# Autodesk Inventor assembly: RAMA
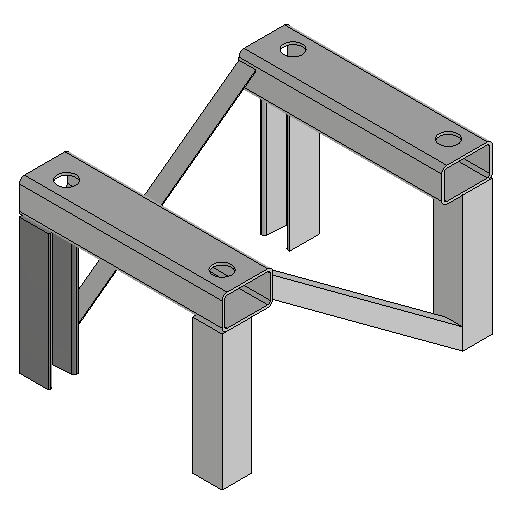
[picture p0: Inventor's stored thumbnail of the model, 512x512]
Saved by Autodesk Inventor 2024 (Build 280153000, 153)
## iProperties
Company: ATC
_FrameDoc: Frame Assembly
_Version: 25.0.0
Created: 2023-03
Part Number: RAMA
Document SubType Name: Assembly
Designer: Andrzej Jaskulski
Checked By: A.J.
Engr Approved By: Andrzej Jaskulski
Mfg Approved By: Andrzej Jaskulski
Authority: A.J.
Author: Andrzej Jaskulski
Title: A.J.: Kurs R2024-MEP
Revision Number: 1/24
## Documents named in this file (10)
- C:\Users\AndJas\Documents\R2024-MEP\Obszar roboczy\SPEC\GOTOWE\SPEC-GOTOWE\Rama\RAMA.iam
- C:\Users\AndJas\Documents\R2024-MEP\Obszar roboczy\SPEC\GOTOWE\SPEC-GOTOWE\Rama\SZKIELET.ipt
- C:\Users\AndJas\Documents\R2024-MEP\Obszar roboczy\SPEC\GOTOWE\SPEC-GOTOWE\Rama\PN C 35x35-01.ipt
- C:\Users\AndJas\Documents\R2024-MEP\Obszar roboczy\SPEC\GOTOWE\SPEC-GOTOWE\Rama\PN C 35x35-02.ipt
- C:\Users\AndJas\Documents\R2024-MEP\Obszar roboczy\SPEC\GOTOWE\SPEC-GOTOWE\Rama\PN C 35x35-03.ipt
- C:\Users\AndJas\Documents\R2024-MEP\Obszar roboczy\SPEC\GOTOWE\SPEC-GOTOWE\Rama\PN C 35x35-04.ipt
- C:\Users\AndJas\Documents\R2024-MEP\Obszar roboczy\SPEC\GOTOWE\SPEC-GOTOWE\Rama\PN 60 x 40 x 3-05.ipt
- C:\Users\AndJas\Documents\R2024-MEP\Obszar roboczy\SPEC\GOTOWE\SPEC-GOTOWE\Rama\PN 60 x 40 x 3-06.ipt
- C:\Users\AndJas\Documents\R2024-MEP\Obszar roboczy\SPEC\GOTOWE\SPEC-GOTOWE\Rama\PN L20x20x3-7.ipt
- C:\Users\AndJas\Documents\R2024-MEP\Obszar roboczy\SPEC\GOTOWE\SPEC-GOTOWE\Rama\PN L20x20x3-8.ipt
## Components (9 placed, 9 different names)
1. SZKIELET:1
2. PN C 35x35-01:1
3. PN C 35x35-02:1
4. PN C 35x35-03:1
5. PN C 35x35-04:1
6. PN 60 x 40 x 3-05:1
7. PN 60 x 40 x 3-06:1
8. PN L20x20x3-7:1
9. PN L20x20x3-8:1
